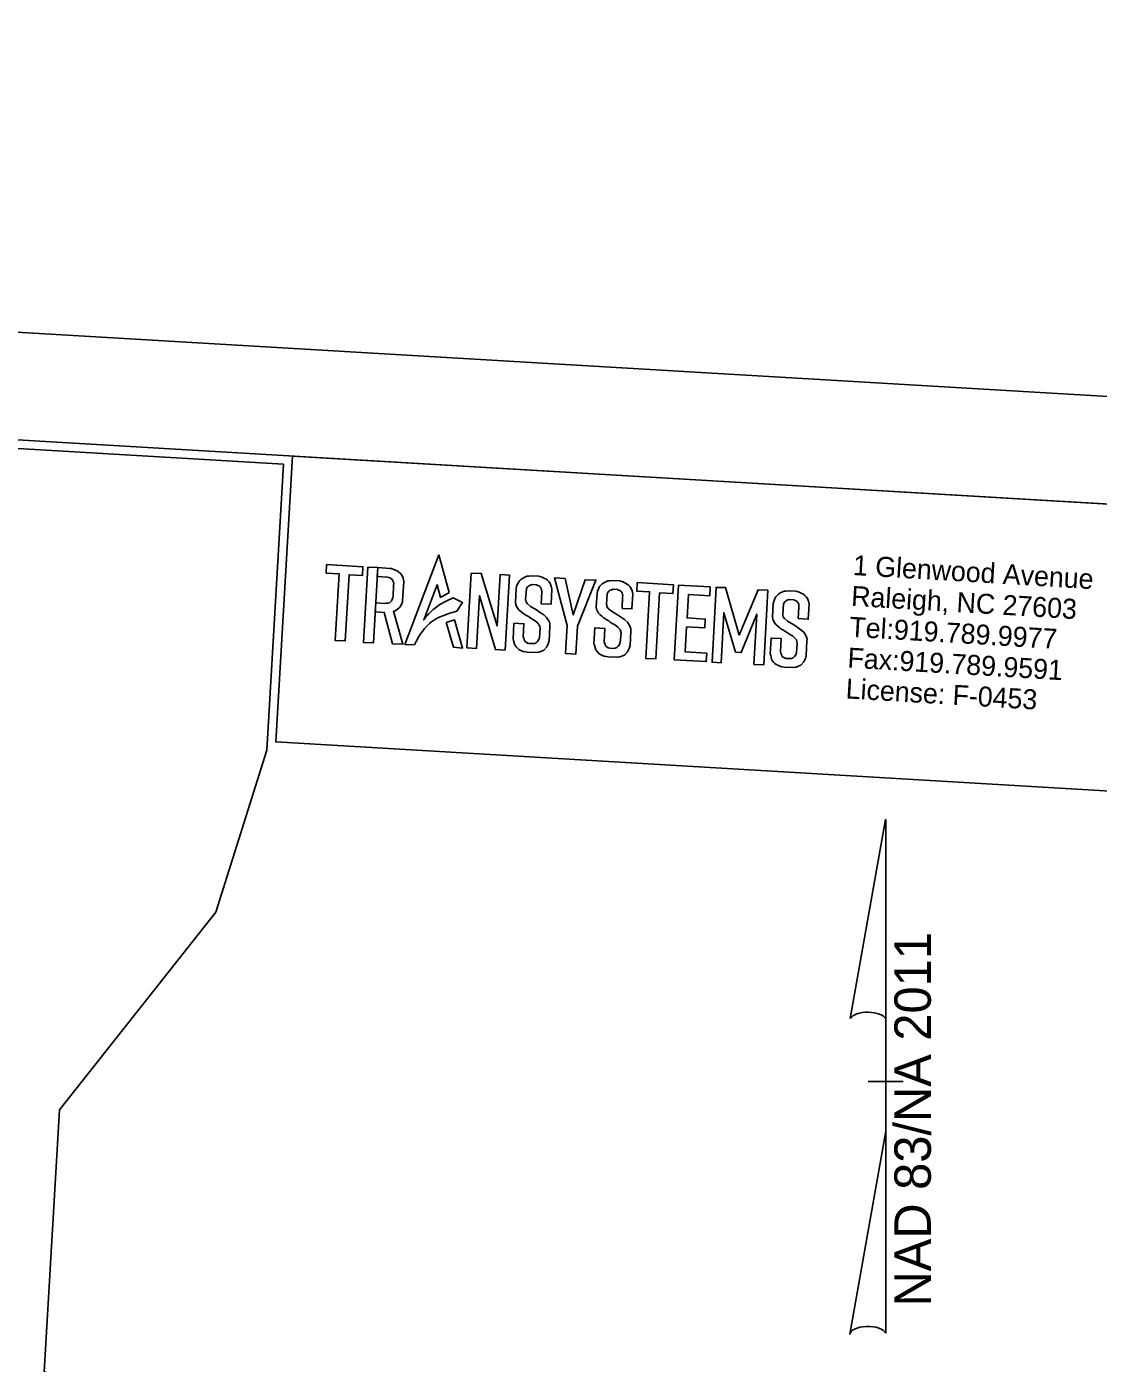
# Model space of a CAD drawing. Extents: x 2012145 to 2014096, y 444445 to 445643.
# Drawn here: x 2013608.3 to 2013858, y 445331.9 to 445643.1 of the extents above; entities that cross this region are included whole.
import ezdxf

# ---------------------------------------------------------------- set-up
doc = ezdxf.new("R2010")
doc.units = 0
for name, color, linetype in [('Old_Level_1', 7, 'Continuous'), ('Old_Level_2', 7, 'Continuous'), ('Old_Level_58', 7, 'Continuous'), ('Prop North Arrow NAD83 for Plan Sheets CELL', 7, 'Continuous'), ('Sheet Clip Boundary CELL', 7, 'Continuous'), ('Sheet Plan And Profile CELL', 7, 'Continuous'), ('Sheet Plot Border Outside CELL', 7, 'Continuous')]:
    doc.layers.add(name, color=color, linetype=linetype)

msp = doc.modelspace()

# ---------------------------------------------------------------- linework, layer by layer
at = {"layer": 'Old_Level_1'}
for points in [[(2013704.33, 445520.19), (2013696.42, 445499.28), (2013698.64, 445499.16), (2013699.03, 445499.98), (2013699.67, 445501.11), (2013700.02, 445501.72), (2013700.42, 445502.23), (2013700.99, 445502.96), (2013701.34, 445503.41), (2013701.75, 445503.78), (2013702.15, 445504.14), (2013702.66, 445504.61), (2013703.09, 445504.86), (2013703.52, 445505.16), (2013704.1, 445505.45), (2013704.61, 445505.7), (2013705.85, 445506.2), (2013706.88, 445506.55), (2013708.55, 445507.01), (2013709.81, 445509.09), (2013707.69, 445510.17), (2013706.01, 445509.38), (2013704.58, 445508.56), (2013703.56, 445507.82), (2013703.01, 445507.42), (2013702.44, 445506.89), (2013701.88, 445506.35), (2013701.45, 445505.95), (2013701.04, 445505.33), (2013700.81, 445504.98), (2013703.93, 445513.19), (2013704.75, 445510.25), (2013706.72, 445511.39)], [(2013678.18, 445517.88), (2013686.63, 445517.39), (2013686.51, 445515.32), (2013683.41, 445515.5), (2013682.52, 445500.1), (2013680.17, 445500.24), (2013681.07, 445515.73), (2013678.1, 445515.91)], [(2013687.78, 445517.3), (2013690.1, 445517.17), (2013689.08, 445499.63), (2013686.77, 445499.77)], [(2013689.98, 445515.09), (2013692.36, 445514.95), (2013692.66, 445514.88), (2013693.05, 445514.7), (2013693.36, 445514.46), (2013693.58, 445514.17), (2013693.71, 445513.84), (2013693.82, 445513.57), (2013693.78, 445512.99), (2013693.65, 445510.51), (2013693.57, 445510.18), (2013693.46, 445509.74), (2013693.31, 445509.46), (2013693.09, 445509.21), (2013692.81, 445509.01), (2013692.38, 445508.88), (2013692.05, 445508.86), (2013691.72, 445508.84), (2013689.62, 445508.95), (2013689.51, 445506.85), (2013691.61, 445506.73), (2013693.55, 445499.44), (2013695.97, 445499.33), (2013693.76, 445507.01), (2013694.15, 445507.12), (2013694.71, 445507.49), (2013695.23, 445507.99), (2013695.61, 445508.6), (2013695.87, 445509.22), (2013695.86, 445509.41), (2013696.17, 445513.97), (2013696.01, 445514.72), (2013695.69, 445515.42), (2013695.31, 445515.92), (2013694.64, 445516.43), (2013693.98, 445516.69), (2013693.31, 445516.96), (2013692.91, 445516.98), (2013690.1, 445517.17)], [(2013711.86, 445515.92), (2013710.85, 445498.49), (2013713.08, 445498.36), (2013713.79, 445510.62), (2013717.51, 445498.08), (2013719.76, 445497.97), (2013720.77, 445515.45), (2013718.59, 445515.57), (2013717.9, 445503.61), (2013714.21, 445515.79)], [(2013728.16, 445508.78), (2013730.47, 445508.65), (2013730.67, 445512.12), (2013730.52, 445512.83), (2013730.27, 445513.44), (2013730, 445513.85), (2013729.65, 445514.22), (2013729.23, 445514.53), (2013728.81, 445514.73), (2013728.81, 445514.73), (2013728.36, 445514.95), (2013727.89, 445515.1), (2013727.57, 445515.19), (2013725.83, 445515.26), (2013725.29, 445515.2), (2013724.83, 445515.15), (2013724.36, 445514.94), (2013723.94, 445514.75), (2013723.53, 445514.49), (2013723.2, 445514.2), (2013722.94, 445513.84), (2013722.72, 445513.46), (2013722.43, 445512.78), (2013722.35, 445512.27), (2013722.16, 445509.11), (2013722.25, 445508.62), (2013722.45, 445508.12), (2013722.71, 445507.69), (2013722.99, 445507.36), (2013723.42, 445506.99), (2013723.85, 445506.62), (2013724.12, 445506.38), (2013724.59, 445506.13), (2013725.06, 445505.87), (2013725.43, 445505.6), (2013725.86, 445505.29), (2013726.37, 445504.99), (2013726.79, 445504.75), (2013727.2, 445504.41), (2013727.49, 445504.09), (2013727.73, 445503.84), (2013727.85, 445503.35), (2013727.93, 445503.05), (2013727.76, 445500.82), (2013727.57, 445500.34), (2013727.3, 445499.94), (2013726.96, 445499.67), (2013726.59, 445499.53), (2013726.25, 445499.48), (2013725.29, 445499.51), (2013724.97, 445499.62), (2013724.65, 445499.83), (2013724.34, 445500.05), (2013724.21, 445500.39), (2013724.09, 445500.73), (2013723.99, 445501.01), (2013724.14, 445504.11), (2013721.81, 445504.22), (2013721.63, 445500.52), (2013721.73, 445500.23), (2013721.95, 445499.35), (2013722.11, 445499.05), (2013722.34, 445498.72), (2013722.7, 445498.32), (2013722.99, 445498.11), (2013723.42, 445497.9), (2013723.57, 445497.83), (2013723.99, 445497.62), (2013724.52, 445497.54), (2013724.91, 445497.48), (2013727.05, 445497.4), (2013727.65, 445497.51), (2013728.5, 445497.83), (2013728.78, 445497.94), (2013729.45, 445498.7), (2013729.83, 445499.46), (2013730.03, 445500.16), (2013730.18, 445503.58), (2013730.2, 445504.05), (2013730.09, 445504.44), (2013729.92, 445504.8), (2013729.42, 445505.59), (2013728.75, 445506.19), (2013727.81, 445506.82), (2013727.09, 445507.31), (2013725.68, 445508.16), (2013724.96, 445508.77), (2013724.65, 445509.21), (2013724.59, 445509.5), (2013724.53, 445509.78), (2013724.72, 445512.21), (2013724.86, 445512.45), (2013725, 445512.7), (2013725.19, 445512.84), (2013725.43, 445513.03), (2013725.69, 445513.12), (2013725.96, 445513.21), (2013726.1, 445513.17), (2013726.12, 445513.24), (2013727.08, 445513.17), (2013727.35, 445513.05), (2013727.62, 445512.92), (2013727.89, 445512.8), (2013728.01, 445512.6), (2013728.18, 445512.31), (2013728.25, 445512.03), (2013728.33, 445511.74), (2013728.3, 445511.44)], [(2013733.79, 445514.64), (2013731.25, 445514.79), (2013734.23, 445503.71), (2013733.87, 445497.18), (2013736.26, 445497.05), (2013736.61, 445503.53), (2013740.91, 445514.26), (2013738.41, 445514.34), (2013735.62, 445506.15)], [(2013747, 445507.69), (2013749.31, 445507.55), (2013749.51, 445511.02), (2013749.36, 445511.74), (2013749.11, 445512.35), (2013748.84, 445512.75), (2013748.49, 445513.12), (2013748.07, 445513.43), (2013747.65, 445513.63), (2013747.65, 445513.63), (2013747.21, 445513.85), (2013746.73, 445514), (2013746.41, 445514.1), (2013744.67, 445514.17), (2013744.13, 445514.11), (2013743.67, 445514.06), (2013743.2, 445513.84), (2013742.78, 445513.66), (2013742.37, 445513.4), (2013742.04, 445513.1), (2013741.78, 445512.75), (2013741.56, 445512.37), (2013741.27, 445511.69), (2013741.19, 445511.18), (2013741, 445508.01), (2013741.09, 445507.53), (2013741.29, 445507.03), (2013741.55, 445506.6), (2013741.83, 445506.27), (2013742.26, 445505.9), (2013742.69, 445505.52), (2013742.96, 445505.29), (2013743.43, 445505.03), (2013743.9, 445504.78), (2013744.27, 445504.51), (2013744.7, 445504.19), (2013745.21, 445503.9), (2013745.63, 445503.65), (2013746.04, 445503.31), (2013746.33, 445503), (2013746.57, 445502.75), (2013746.69, 445502.26), (2013746.77, 445501.96), (2013746.6, 445499.72), (2013746.41, 445499.25), (2013746.14, 445498.85), (2013745.8, 445498.58), (2013745.43, 445498.43), (2013745.09, 445498.38), (2013744.13, 445498.42), (2013743.81, 445498.53), (2013743.49, 445498.74), (2013743.18, 445498.95), (2013743.05, 445499.3), (2013742.93, 445499.64), (2013742.84, 445499.91), (2013742.98, 445503.02), (2013740.65, 445503.13), (2013740.47, 445499.43), (2013740.57, 445499.14), (2013740.79, 445498.26), (2013740.95, 445497.96), (2013741.18, 445497.63), (2013741.54, 445497.23), (2013741.83, 445497.02), (2013742.26, 445496.81), (2013742.41, 445496.74), (2013742.83, 445496.53), (2013743.36, 445496.44), (2013743.75, 445496.38), (2013745.89, 445496.31), (2013746.49, 445496.42), (2013747.34, 445496.74), (2013747.62, 445496.85), (2013748.29, 445497.6), (2013748.67, 445498.37), (2013748.87, 445499.07), (2013749.02, 445502.49), (2013749.04, 445502.96), (2013748.93, 445503.34), (2013748.76, 445503.71), (2013748.26, 445504.5), (2013747.59, 445505.1), (2013746.65, 445505.73), (2013745.93, 445506.22), (2013744.52, 445507.07), (2013743.8, 445507.67), (2013743.5, 445508.11), (2013743.43, 445508.4), (2013743.37, 445508.69), (2013743.56, 445511.11), (2013743.7, 445511.36), (2013743.84, 445511.61), (2013744.03, 445511.75), (2013744.27, 445511.93), (2013744.53, 445512.02), (2013744.8, 445512.12), (2013744.94, 445512.08), (2013744.96, 445512.15), (2013745.92, 445512.08), (2013746.19, 445511.95), (2013746.46, 445511.83), (2013746.73, 445511.7), (2013746.85, 445511.5), (2013747.02, 445511.21), (2013747.09, 445510.93), (2013747.17, 445510.65), (2013747.14, 445510.35)], [(2013750.52, 445513.68), (2013758.97, 445513.19), (2013758.85, 445511.12), (2013755.75, 445511.3), (2013754.85, 445495.9), (2013752.51, 445496.04), (2013753.41, 445511.54), (2013750.44, 445511.71)], [(2013767.56, 445512.68), (2013760.19, 445513.11), (2013759.18, 445495.71), (2013766.64, 445495.28), (2013766.75, 445497.25), (2013761.72, 445497.54), (2013762.05, 445503.37), (2013766.26, 445503.13), (2013766.38, 445505.2), (2013762.14, 445505.45), (2013762.46, 445510.93), (2013767.46, 445510.64)], [(2013774.29, 445501.42), (2013771.12, 445512.54), (2013768.91, 445512.57), (2013767.97, 445495.13), (2013770.07, 445495.02), (2013770.7, 445506.68), (2013773.44, 445497.52), (2013774.78, 445497.4), (2013778.38, 445506.34), (2013777.74, 445494.64), (2013780.01, 445494.51), (2013780.97, 445511.9), (2013778.68, 445512.03)], [(2013788.07, 445505.3), (2013790.37, 445505.17), (2013790.57, 445508.64), (2013790.42, 445509.36), (2013790.18, 445509.96), (2013789.9, 445510.37), (2013789.55, 445510.74), (2013789.13, 445511.05), (2013788.71, 445511.25), (2013788.71, 445511.25), (2013788.27, 445511.47), (2013787.79, 445511.62), (2013787.48, 445511.72), (2013785.73, 445511.79), (2013785.2, 445511.73), (2013784.74, 445511.67), (2013784.26, 445511.46), (2013783.84, 445511.28), (2013783.43, 445511.01), (2013783.11, 445510.72), (2013782.84, 445510.37), (2013782.63, 445509.99), (2013782.33, 445509.31), (2013782.25, 445508.79), (2013782.06, 445505.63), (2013782.15, 445505.15), (2013782.35, 445504.64), (2013782.61, 445504.22), (2013782.89, 445503.89), (2013783.32, 445503.52), (2013783.75, 445503.14), (2013784.02, 445502.91), (2013784.49, 445502.65), (2013784.96, 445502.4), (2013785.34, 445502.12), (2013785.76, 445501.81), (2013786.27, 445501.51), (2013786.69, 445501.27), (2013787.1, 445500.93), (2013787.39, 445500.62), (2013787.63, 445500.37), (2013787.75, 445499.88), (2013787.83, 445499.57), (2013787.66, 445497.34), (2013787.47, 445496.87), (2013787.2, 445496.46), (2013786.86, 445496.19), (2013786.5, 445496.05), (2013786.15, 445496), (2013785.19, 445496.04), (2013784.87, 445496.15), (2013784.56, 445496.36), (2013784.24, 445496.57), (2013784.12, 445496.91), (2013784, 445497.26), (2013783.9, 445497.53), (2013784.05, 445500.64), (2013781.71, 445500.75), (2013781.53, 445497.04), (2013781.64, 445496.76), (2013781.85, 445495.88), (2013782.01, 445495.58), (2013782.25, 445495.24), (2013782.6, 445494.85), (2013782.9, 445494.64), (2013783.32, 445494.43), (2013783.47, 445494.35), (2013783.89, 445494.15), (2013784.42, 445494.06), (2013784.81, 445494), (2013786.95, 445493.93), (2013787.55, 445494.03), (2013788.4, 445494.36), (2013788.69, 445494.47), (2013789.35, 445495.22), (2013789.74, 445495.99), (2013789.93, 445496.69), (2013790.08, 445500.11), (2013790.1, 445500.58), (2013789.99, 445500.96), (2013789.82, 445501.33), (2013789.33, 445502.12), (2013788.65, 445502.71), (2013787.71, 445503.35), (2013787, 445503.84), (2013785.58, 445504.69), (2013784.86, 445505.29), (2013784.56, 445505.73), (2013784.5, 445506.02), (2013784.44, 445506.31), (2013784.63, 445508.73), (2013784.76, 445508.98), (2013784.9, 445509.23), (2013785.09, 445509.37), (2013785.33, 445509.55), (2013785.6, 445509.64), (2013785.86, 445509.73), (2013786.01, 445509.7), (2013786.03, 445509.77), (2013786.98, 445509.7), (2013787.25, 445509.57), (2013787.52, 445509.45), (2013787.79, 445509.32), (2013787.91, 445509.12), (2013788.08, 445508.83), (2013788.16, 445508.55), (2013788.23, 445508.27), (2013788.21, 445507.97)], [(2013706.01, 445504.36), (2013707.97, 445505.01), (2013709.85, 445498.45), (2013707.76, 445498.65)]]:
    msp.add_lwpolyline(points, close=True, dxfattribs=at)
at = {"layer": 'Old_Level_58'}
msp.add_lwpolyline([(2013670.27, 445543.15), (2013869.97, 445531.38), (2013866.05, 445464.8), (2013666.34, 445476.57)], close=True, dxfattribs=at)
at = {"layer": 'Prop North Arrow NAD83 for Plan Sheets CELL'}
for p, q in [((2013800.18, 445412.2), (2013808.38, 445458.55)), ((2013808.43, 445458.55), (2013808.38, 445458.55)), ((2013808.43, 445458.55), (2013808.38, 445458.55)), ((2013808.43, 445458.55), (2013808.43, 445410.75)), ((2013808.43, 445385.95), (2013808.43, 445412.15)), ((2013808.43, 445410.75), (2013808.43, 445412.1)), ((2013804.43, 445397.55), (2013804.38, 445397.55)), ((2013807.98, 445397.55), (2013804.43, 445397.55)), ((2013804.48, 445397.55), (2013812.48, 445397.55)), ((2013808.43, 445385.95), (2013800.08, 445338.7)), ((2013808.48, 445338.9), (2013808.43, 445385.95))]:
    msp.add_line(p, q, dxfattribs=at)
for centre, start_param, end_param in [((2013804.32, 445411.7), 0.216388, 2.908219), ((2013804.32, 445338.53), 0.201328, 3.141593)]:
    msp.add_ellipse(centre, major_axis=(4.23, -0.03), ratio=0.461098, start_param=start_param, end_param=end_param, dxfattribs=at)
at = {"layer": 'Sheet Clip Boundary CELL'}
msp.add_lwpolyline([(2013668.15, 445541.27), (2012675.49, 445599.79), (2012666.5, 445450.87), (2012644.05, 445070.04), (2012629.92, 444830.46), (2012620.01, 444659.47), (2012673.15, 444619.9), (2012617.31, 444617.99), (2012613.72, 444555.61), (2014006.01, 444473.54), (2014041.96, 445083.42), (2013915.76, 445258.44), (2013612.37, 445329.9), (2013615.96, 445390.93), (2013652.41, 445436.93), (2013664.23, 445474.69)], close=True, dxfattribs=at)
at = {"layer": 'Sheet Plan And Profile CELL'}
msp.add_lwpolyline([(2014069.67, 445519.6), (2012572.27, 445607.87), (2012510.48, 444559.69), (2014007.88, 444471.42)], close=True, dxfattribs=at)
at = {"layer": 'Sheet Plot Border Outside CELL'}
msp.add_lwpolyline([(2012334.32, 444545.03), (2014031.37, 444445), (2014096.1, 445543.09), (2012399.05, 445643.13)], close=True, dxfattribs=at)

# ---------------------------------------------------------------- texts
at = {"layer": 'Old_Level_2'}
for s, p in [('1 Glenwood Avenue', (2013800.71, 445515.46)), ('Raleigh, NC 27603', (2013800.29, 445508.28)), ('Tel:919.789.9977 ', (2013799.86, 445501.09)), ('Fax:919.789.9591', (2013799.44, 445493.91)), ('License: F-0453', (2013799.02, 445486.73))]:
    msp.add_text(s, height=4.6576, rotation=356.6264, dxfattribs=at).set_placement(p)
at = {"layer": 'Prop North Arrow NAD83 for Plan Sheets CELL'}
msp.add_text('NAD 83/NA 2011', height=8.5, rotation=90, dxfattribs=at).set_placement((2013818.95, 445345.12))

doc.saveas('drawing.dxf')
